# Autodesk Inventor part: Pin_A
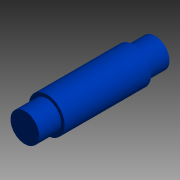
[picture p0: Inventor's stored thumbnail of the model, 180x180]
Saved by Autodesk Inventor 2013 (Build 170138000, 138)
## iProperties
Shininess: 0.0
Length Units: 11272
Angle Units: 11279
Time Units: 11290
Mass Units: 11283
Length Display Precision: 2
Angle Display Precision: 1
Compacted: True
Created: 1999-05
Part Number: Pin_A
Document SubType Name: Modeling
Designer: Administrator
Density: 7.84 g/cm^3
Material: Steel, High Strength Low Alloy
Mass: 9.6691 g
Surface Area: 7.61176 cm^2
Volume: 1.2333 cm^3
Density: 0.0
Volumn: 0.0
Area: 0.0
PropertySet Name: Model Information
Control State: 0
Master: False
Checked Out: False
Author: Administrator
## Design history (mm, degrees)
node "y-z Plane"
  node "x-z Plane"
  node "x-y Plane"
node "Extrusion1" dims "d1" = 19.05, "d2" = 0
  sketch "Sketch1"
    geometry: C1 r 3.937 at (0, 0); 1 further point
    constraints: 1 centre point, 1 coincident
    dimensions: "d0" = 7.874 diameter of C1
node "Extrusion2" dims "d4" = 4.826, "d5" = 0
  sketch "Sketch2"
    geometry: C1 r 3.937 at (0, 0) reference; C2 r 3.175 at (0, 0)
    constraints: 1 centre point
    dimensions: "d3" = 6.35 diameter of C2
node "Extrusion3" dims "d7" = 4.826, "d8" = 0
  sketch "Sketch3"
    geometry: C1 r 3.937 at (0, 0) reference; C2 r 3.175 at (0, 0)
    constraints: 1 centre point
    dimensions: "d6" = 6.35 diameter of C2
body "Solid1"
